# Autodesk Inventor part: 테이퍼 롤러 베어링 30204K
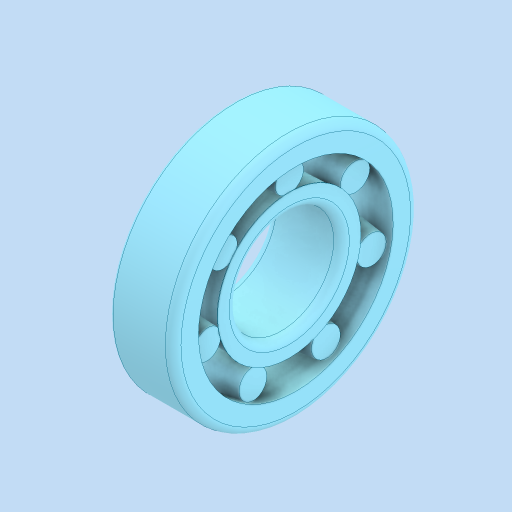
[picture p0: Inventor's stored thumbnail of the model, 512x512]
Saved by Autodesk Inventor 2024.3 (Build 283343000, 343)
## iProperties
Created: 2026-01
Part Number: 테이퍼 롤러 베어링 30204K
Material: 강철, 연강
Description: 테이퍼 롤러 베어링
Document SubType Name: Modeling
Designer: PC2-02
Density: 7.85 g/cm^3
Appearance: 기본값
Author: jhkim
Sending System: Autodesk Inventor 2026
Preprocessor: ST-DEVELOPER v20.1
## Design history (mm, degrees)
node "테이퍼 롤러 베어링 30204K1"
node "솔리드1"
node "솔리드2"
body "Solid1"
node "Solid1:1"
